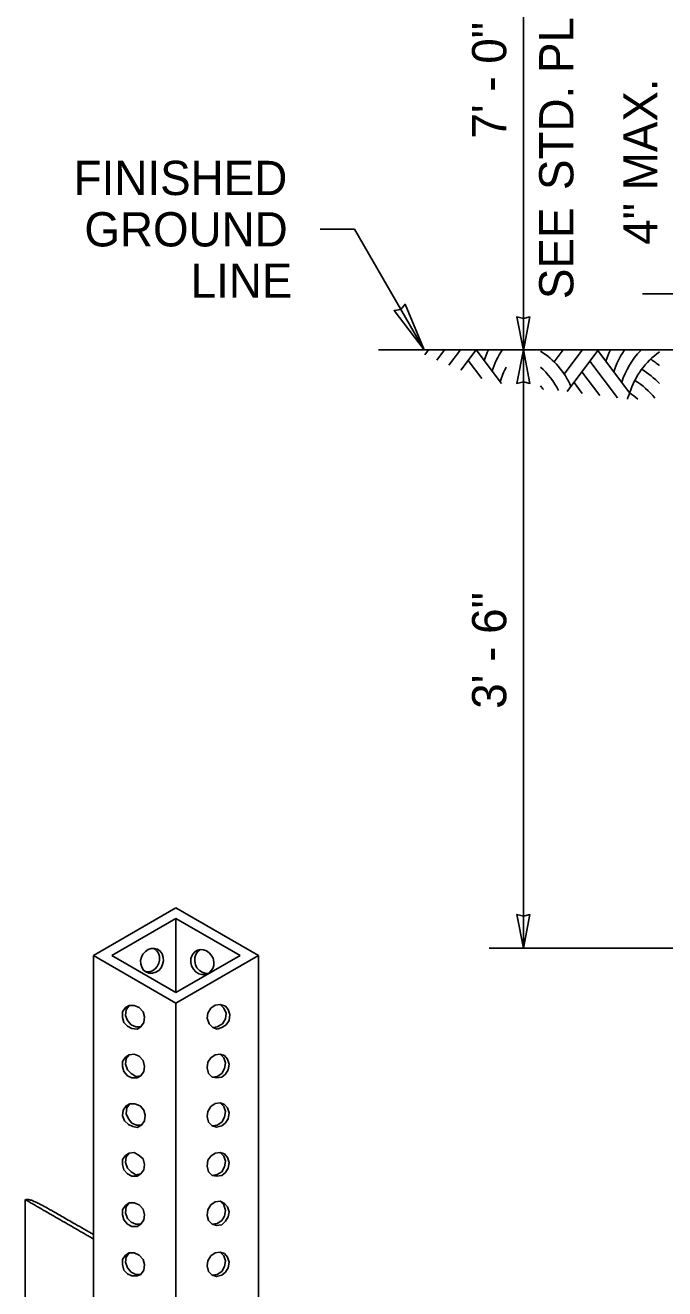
# Model space of a CAD drawing. Extents: x 99862 to 103680, y 99470 to 102076.
# Drawn here: x 101650 to 101949, y 100895 to 101485 of the extents above; entities that cross this region are included whole.
import ezdxf

# ---------------------------------------------------------------- set-up
doc = ezdxf.new("R2010")
doc.units = 0
for name, color, linetype in [('Level 1', 7, 'Continuous'), ('Level 15', 7, 'Continuous'), ('Level 2', 7, 'Continuous'), ('Level 20', 7, 'Continuous'), ('Level 27', 7, 'Continuous'), ('Level 4', 7, 'Continuous'), ('Level 5', 7, 'Continuous')]:
    doc.layers.add(name, color=color, linetype=linetype)

msp = doc.modelspace()

# ---------------------------------------------------------------- linework, layer by layer
at = {"layer": 'Level 1'}
for p, q in [((101837.2, 101331.35), (101838.99, 101333.74)), ((101842.83, 101328.96), (101846.41, 101333.74)), ((101848.46, 101326.57), (101853.84, 101333.74)), ((101854.09, 101324.18), (101861.26, 101333.74)), ((101861.26, 101333.74), (101873.05, 101318.02)), ((101857.55, 101328.79), (101863.91, 101320.31))]:
    msp.add_line(p, q, dxfattribs=at)
for centre, start, end in [((101810.6, 101302.55), 56.0955, 56.09634), ((101900.78, 101317.4), 154.22656, 162.3566), ((101904.5, 101312.45), 145.49104, 162.3566), ((101871.19, 101301.38), 23.9418, 57.64973), ((101908.21, 101307.5), 151.13992, 162.3566), ((101866.29, 101297.6), 27.04099, 48.27306), ((101862.58, 101292.65), 36.71615, 40.14882)]:
    msp.add_arc(centre, 37.58, start, end, dxfattribs=at)
at = {"layer": 'Level 15'}
for p, q in [((101804.37, 101390.03), (101788.37, 101390.03)), ((101836.87, 101333.74), (101804.37, 101390.03))]:
    msp.add_line(p, q, dxfattribs=at)
for points in [[(101883.3, 101634.09), (101883.3, 101333.39)], [(101938.91, 101359.95), (102030.24, 101359.95)], [(101883.3, 101333.74), (101883.3, 101054.17)], [(101867.3, 101054.17), (101993.49, 101054.17)]]:
    msp.add_lwpolyline(points, dxfattribs=at)
for points in [[(101836.87, 101333.74), (101822.87, 101352.02), (101825.98, 101352.59), (101828.04, 101355)], [(101883.3, 101333.39), (101886.38, 101349.12), (101883.3, 101348.39), (101880.22, 101349.12)], [(101883.3, 101333.74), (101886.38, 101318.01), (101883.3, 101318.74), (101880.22, 101318.01)], [(101883.3, 101054.17), (101886.38, 101069.89), (101883.3, 101069.17), (101880.22, 101069.89)]]:
    msp.add_lwpolyline(points, close=True, dxfattribs=at)
at = {"layer": 'Level 2'}
for p, q in [((101682.38, 101050.75), (101720.9, 101072.98)), ((101690.94, 101050.75), (101720.9, 101068.04)), ((101720.8, 101068.1), (101720.8, 101033.93)), ((101720.9, 101072.98), (101759.42, 101050.75)), ((101720.9, 101068.04), (101750.86, 101050.75)), ((101720.9, 101028.51), (101682.38, 101050.75)), ((101682.38, 100920.34), (101682.38, 101050.75)), ((101720.9, 101033.45), (101690.94, 101050.75)), ((101759.42, 101050.75), (101720.9, 101028.51)), ((101750.86, 101050.75), (101720.9, 101033.45)), ((101759.42, 100875.03), (101759.42, 101050.75)), ((101697.28, 101026.43), (101695.9, 101024.42)), ((101698.99, 101027.43), (101697.28, 101026.43)), ((101698.99, 101027.43), (101697.62, 101025.42)), ((101697.62, 101025.42), (101698.99, 101027.43)), ((101701.39, 101027.43), (101698.99, 101027.43)), ((101703.79, 101026.43), (101701.39, 101027.43)), ((101705.51, 101024.42), (101703.79, 101026.43)), ((101720.9, 100850.43), (101720.9, 101028.51)), ((101739.21, 101027.46), (101737.16, 101026.12)), ((101741.62, 101027.79), (101739.21, 101027.46)), ((101743.33, 101026.12), (101741.62, 101027.79)), ((101741.62, 101027.79), (101743.33, 101026.12)), ((101744.02, 101027.12), (101741.62, 101027.79)), ((101745.39, 101025.45), (101744.02, 101027.12)), ((101695.9, 101024.42), (101695.9, 101021.74)), ((101695.9, 101021.74), (101696.59, 101019.39)), ((101697.62, 101025.42), (101697.28, 101022.74)), ((101697.28, 101022.74), (101697.62, 101025.42)), ((101697.28, 101022.74), (101698.3, 101020.39)), ((101698.3, 101020.39), (101697.28, 101022.74)), ((101698.3, 101020.39), (101700.02, 101018.38)), ((101700.02, 101018.38), (101698.3, 101020.39)), ((101706.19, 101022.07), (101705.51, 101024.42)), ((101705.85, 101019.39), (101706.19, 101022.07)), ((101735.78, 101023.77), (101735.44, 101021.42)), ((101735.44, 101021.42), (101736.47, 101018.74)), ((101737.16, 101026.12), (101735.78, 101023.77)), ((101742.65, 101018.74), (101744.02, 101021.09)), ((101744.02, 101021.09), (101742.65, 101018.74)), ((101744.36, 101023.77), (101743.33, 101026.12)), ((101743.33, 101026.12), (101744.36, 101023.77)), ((101744.02, 101021.09), (101744.36, 101023.77)), ((101744.36, 101023.77), (101744.02, 101021.09)), ((101744.36, 101018.41), (101745.73, 101020.42)), ((101746.08, 101023.1), (101745.39, 101025.45)), ((101745.73, 101020.42), (101746.08, 101023.1)), ((101696.59, 101019.39), (101698.3, 101017.71)), ((101698.3, 101017.71), (101700.36, 101016.71)), ((101700.02, 101018.38), (101702.08, 101017.38)), ((101702.08, 101017.38), (101700.02, 101018.38)), ((101700.36, 101016.71), (101702.76, 101016.37)), ((101702.08, 101017.38), (101704.48, 101017.38)), ((101704.48, 101017.38), (101702.08, 101017.38)), ((101702.76, 101016.37), (101704.48, 101017.38)), ((101704.48, 101017.38), (101705.85, 101019.39)), ((101736.47, 101018.74), (101738.19, 101017.07)), ((101738.19, 101017.07), (101740.24, 101017.4)), ((101740.24, 101017.4), (101738.19, 101017.07)), ((101738.19, 101017.07), (101740.24, 101016.39)), ((101740.24, 101017.4), (101742.65, 101018.74)), ((101742.65, 101018.74), (101740.24, 101017.4)), ((101740.24, 101016.39), (101742.3, 101017.07)), ((101742.3, 101017.07), (101744.36, 101018.41)), ((101697.28, 101003.3), (101695.9, 101001.29)), ((101698.99, 101004.3), (101697.28, 101003.3)), ((101697.62, 101002.63), (101697.28, 100999.95)), ((101697.28, 100999.95), (101697.62, 101002.63)), ((101698.99, 101004.3), (101697.62, 101002.63)), ((101697.62, 101002.63), (101698.99, 101004.3)), ((101701.39, 101004.64), (101698.99, 101004.3)), ((101703.79, 101003.63), (101701.39, 101004.64)), ((101705.51, 101001.62), (101703.79, 101003.63)), ((101737.16, 101002.99), (101735.78, 101000.98)), ((101739.21, 101004.33), (101737.16, 101002.99)), ((101741.62, 101004.66), (101739.21, 101004.33)), ((101743.33, 101002.99), (101741.62, 101004.66)), ((101743.67, 101003.99), (101741.62, 101004.66)), ((101741.62, 101004.66), (101743.33, 101002.99)), ((101744.02, 101000.64), (101743.33, 101002.99)), ((101743.33, 101002.99), (101744.02, 101000.64)), ((101745.05, 101002.32), (101743.67, 101003.99)), ((101695.9, 101001.29), (101695.9, 100998.94)), ((101695.9, 100998.94), (101696.59, 100996.59)), ((101697.28, 100999.95), (101698.3, 100997.26)), ((101698.3, 100997.26), (101697.28, 100999.95)), ((101698.3, 100997.26), (101700.02, 100995.59)), ((101700.02, 100995.59), (101698.3, 100997.26)), ((101706.19, 100998.94), (101705.51, 101001.62)), ((101705.85, 100996.59), (101706.19, 100998.94)), ((101735.78, 101000.98), (101735.44, 100998.29)), ((101735.44, 100998.29), (101736.13, 100995.61)), ((101742.3, 100995.61), (101743.67, 100997.96)), ((101743.67, 100997.96), (101742.3, 100995.61)), ((101743.67, 100997.96), (101744.02, 101000.64)), ((101744.02, 101000.64), (101743.67, 100997.96)), ((101744.02, 100995.28), (101745.39, 100997.29)), ((101745.73, 100999.97), (101745.05, 101002.32)), ((101745.39, 100997.29), (101745.73, 100999.97)), ((101696.59, 100996.59), (101698.3, 100994.58)), ((101698.3, 100994.58), (101700.36, 100993.58)), ((101700.02, 100995.59), (101702.08, 100994.25)), ((101702.08, 100994.25), (101700.02, 100995.59)), ((101700.36, 100993.58), (101702.76, 100993.58)), ((101702.08, 100994.25), (101704.48, 100994.58)), ((101704.48, 100994.58), (101702.08, 100994.25)), ((101702.76, 100993.58), (101704.48, 100994.58)), ((101704.48, 100994.58), (101705.85, 100996.59)), ((101736.13, 100995.61), (101737.84, 100993.94)), ((101737.84, 100993.94), (101740.24, 100994.27)), ((101740.24, 100994.27), (101737.84, 100993.94)), ((101737.84, 100993.94), (101739.9, 100993.6)), ((101739.9, 100993.6), (101742.3, 100993.94)), ((101740.24, 100994.27), (101742.3, 100995.61)), ((101742.3, 100995.61), (101740.24, 100994.27)), ((101742.3, 100993.94), (101744.02, 100995.28)), ((101697.62, 100980.5), (101696.25, 100978.49)), ((101699.33, 100981.51), (101697.62, 100980.5)), ((101697.96, 100979.5), (101697.62, 100976.82)), ((101697.62, 100976.82), (101697.96, 100979.5)), ((101699.33, 100981.51), (101697.96, 100979.5)), ((101697.96, 100979.5), (101699.33, 100981.51)), ((101701.74, 100981.51), (101699.33, 100981.51)), ((101704.14, 100980.5), (101701.74, 100981.51)), ((101705.85, 100978.49), (101704.14, 100980.5)), ((101737.16, 100980.19), (101735.78, 100977.85)), ((101739.21, 100981.53), (101737.16, 100980.19)), ((101741.62, 100981.87), (101739.21, 100981.53)), ((101743.33, 100980.19), (101741.62, 100981.87)), ((101743.67, 100981.2), (101741.62, 100981.87)), ((101741.62, 100981.87), (101743.33, 100980.19)), ((101744.02, 100977.85), (101743.33, 100980.19)), ((101743.33, 100980.19), (101744.02, 100977.85)), ((101745.05, 100979.52), (101743.67, 100981.2)), ((101745.73, 100977.17), (101745.05, 100979.52)), ((101696.25, 100978.49), (101695.9, 100975.81)), ((101695.9, 100975.81), (101696.93, 100973.46)), ((101696.93, 100973.46), (101698.65, 100971.79)), ((101697.62, 100976.82), (101698.65, 100974.47)), ((101698.65, 100974.47), (101697.62, 100976.82)), ((101698.65, 100974.47), (101700.36, 100972.46)), ((101700.36, 100972.46), (101698.65, 100974.47)), ((101704.82, 100971.45), (101706.19, 100973.46)), ((101706.54, 100976.15), (101705.85, 100978.49)), ((101706.19, 100973.46), (101706.54, 100976.15)), ((101735.78, 100977.85), (101735.44, 100975.5)), ((101735.44, 100975.5), (101736.13, 100972.82)), ((101742.3, 100972.82), (101743.67, 100975.16)), ((101743.67, 100975.16), (101742.3, 100972.82)), ((101743.67, 100975.16), (101744.02, 100977.85)), ((101744.02, 100977.85), (101743.67, 100975.16)), ((101744.02, 100972.48), (101745.39, 100974.49)), ((101745.39, 100974.49), (101745.73, 100977.17)), ((101698.65, 100971.79), (101700.71, 100970.78)), ((101700.36, 100972.46), (101702.42, 100971.45)), ((101702.42, 100971.45), (101700.36, 100972.46)), ((101700.71, 100970.78), (101702.76, 100970.45)), ((101702.42, 100971.45), (101704.82, 100971.45)), ((101704.82, 100971.45), (101702.42, 100971.45)), ((101702.76, 100970.45), (101704.82, 100971.45)), ((101736.13, 100972.82), (101737.84, 100971.14)), ((101737.84, 100971.14), (101740.24, 100971.48)), ((101740.24, 100971.48), (101737.84, 100971.14)), ((101737.84, 100971.14), (101739.9, 100970.47)), ((101739.9, 100970.47), (101742.3, 100971.14)), ((101740.24, 100971.48), (101742.3, 100972.82)), ((101742.3, 100972.82), (101740.24, 100971.48)), ((101742.3, 100971.14), (101744.02, 100972.48)), ((101697.28, 100957.37), (101695.9, 100955.36)), ((101698.99, 100958.38), (101697.28, 100957.37)), ((101697.62, 100956.7), (101697.28, 100954.02)), ((101697.28, 100954.02), (101697.62, 100956.7)), ((101698.99, 100958.38), (101697.62, 100956.7)), ((101697.62, 100956.7), (101698.99, 100958.38)), ((101701.39, 100958.71), (101698.99, 100958.38)), ((101703.79, 100957.37), (101701.39, 100958.71)), ((101705.51, 100955.7), (101703.79, 100957.37)), ((101706.19, 100953.02), (101705.51, 100955.7)), ((101737.16, 100957.06), (101735.78, 100955.05)), ((101739.21, 100958.4), (101737.16, 100957.06)), ((101741.62, 100958.74), (101739.21, 100958.4)), ((101743.33, 100957.06), (101741.62, 100958.74)), ((101743.67, 100958.07), (101741.62, 100958.74)), ((101741.62, 100958.74), (101743.33, 100957.06)), ((101744.02, 100954.72), (101743.33, 100957.06)), ((101743.33, 100957.06), (101744.02, 100954.72)), ((101745.05, 100956.39), (101743.67, 100958.07)), ((101745.73, 100954.05), (101745.05, 100956.39)), ((101695.9, 100955.36), (101695.9, 100953.02)), ((101695.9, 100953.02), (101696.59, 100950.67)), ((101696.59, 100950.67), (101698.3, 100948.66)), ((101697.28, 100954.02), (101698.3, 100951.34)), ((101698.3, 100951.34), (101697.28, 100954.02)), ((101698.3, 100951.34), (101700.02, 100949.66)), ((101700.02, 100949.66), (101698.3, 100951.34)), ((101700.02, 100949.66), (101702.08, 100948.32)), ((101702.08, 100948.32), (101700.02, 100949.66)), ((101704.48, 100948.66), (101705.85, 100950.67)), ((101705.85, 100950.67), (101706.19, 100953.02)), ((101735.78, 100955.05), (101735.44, 100952.37)), ((101735.44, 100952.37), (101736.13, 100949.69)), ((101736.13, 100949.69), (101737.84, 100948.01)), ((101740.24, 100948.35), (101742.3, 100949.69)), ((101742.3, 100949.69), (101740.24, 100948.35)), ((101742.3, 100949.69), (101743.67, 100952.03)), ((101743.67, 100952.03), (101742.3, 100949.69)), ((101743.67, 100952.03), (101744.02, 100954.72)), ((101744.02, 100954.72), (101743.67, 100952.03)), ((101744.02, 100949.35), (101745.39, 100951.36)), ((101745.39, 100951.36), (101745.73, 100954.05)), ((101698.3, 100948.66), (101700.36, 100947.65)), ((101700.36, 100947.65), (101702.76, 100947.65)), ((101702.08, 100948.32), (101704.48, 100948.66)), ((101704.48, 100948.66), (101702.08, 100948.32)), ((101702.76, 100947.65), (101704.48, 100948.66)), ((101737.84, 100948.01), (101740.24, 100948.35)), ((101740.24, 100948.35), (101737.84, 100948.01)), ((101737.84, 100948.01), (101739.9, 100947.68)), ((101739.9, 100947.68), (101742.3, 100948.01)), ((101742.3, 100948.01), (101744.02, 100949.35)), ((101697.28, 100933.91), (101695.9, 100931.9)), ((101695.9, 100931.9), (101695.9, 100929.55)), ((101698.99, 100935.25), (101697.28, 100933.91)), ((101697.62, 100933.24), (101697.28, 100930.56)), ((101697.28, 100930.56), (101697.62, 100933.24)), ((101698.99, 100935.25), (101697.62, 100933.24)), ((101697.62, 100933.24), (101698.99, 100935.25)), ((101701.39, 100935.25), (101698.99, 100935.25)), ((101703.79, 100934.24), (101701.39, 100935.25)), ((101705.51, 100932.23), (101703.79, 100934.24)), ((101706.19, 100929.55), (101705.51, 100932.23)), ((101735.78, 100931.92), (101735.44, 100929.24)), ((101737.16, 100934.27), (101735.78, 100931.92)), ((101739.21, 100935.61), (101737.16, 100934.27)), ((101741.62, 100935.94), (101739.21, 100935.61)), ((101743.33, 100934.27), (101741.62, 100935.94)), ((101743.67, 100934.94), (101741.62, 100935.94)), ((101741.62, 100935.94), (101743.33, 100934.27)), ((101744.02, 100931.59), (101743.33, 100934.27)), ((101743.33, 100934.27), (101744.02, 100931.59)), ((101745.05, 100933.26), (101743.67, 100934.94)), ((101745.73, 100930.92), (101745.05, 100933.26)), ((101695.9, 100929.55), (101696.59, 100927.2)), ((101696.59, 100927.2), (101698.3, 100925.19)), ((101697.28, 100930.56), (101698.3, 100927.88)), ((101698.3, 100927.88), (101697.28, 100930.56)), ((101698.3, 100927.88), (101700.02, 100926.2)), ((101700.02, 100926.2), (101698.3, 100927.88)), ((101700.02, 100926.2), (101702.08, 100925.19)), ((101702.08, 100925.19), (101700.02, 100926.2)), ((101704.48, 100925.19), (101705.85, 100927.2)), ((101705.85, 100927.2), (101706.19, 100929.55)), ((101735.44, 100929.24), (101736.13, 100926.89)), ((101736.13, 100926.89), (101737.84, 100925.22)), ((101740.24, 100925.55), (101742.3, 100926.89)), ((101742.3, 100926.89), (101740.24, 100925.55)), ((101742.3, 100926.89), (101743.67, 100928.9)), ((101743.67, 100928.9), (101742.3, 100926.89)), ((101742.3, 100924.88), (101744.02, 100926.56)), ((101743.67, 100928.9), (101744.02, 100931.59)), ((101744.02, 100931.59), (101743.67, 100928.9)), ((101744.02, 100926.56), (101745.39, 100928.57)), ((101745.39, 100928.57), (101745.73, 100930.92)), ((101682.38, 100920.34), (101682.38, 100873.79)), ((101698.3, 100925.19), (101700.36, 100924.19)), ((101700.36, 100924.19), (101702.76, 100924.19)), ((101702.08, 100925.19), (101704.48, 100925.19)), ((101704.48, 100925.19), (101702.08, 100925.19)), ((101702.76, 100924.19), (101704.48, 100925.19)), ((101737.84, 100925.22), (101740.24, 100925.55)), ((101740.24, 100925.55), (101737.84, 100925.22)), ((101737.84, 100925.22), (101739.9, 100924.55)), ((101739.9, 100924.55), (101742.3, 100924.88)), ((101697.28, 100910.78), (101695.9, 100908.77)), ((101695.9, 100908.77), (101695.9, 100906.42)), ((101698.99, 100911.79), (101697.28, 100910.78)), ((101697.62, 100909.77), (101697.28, 100907.43)), ((101697.28, 100907.43), (101697.62, 100909.77)), ((101698.99, 100911.79), (101697.62, 100909.77)), ((101697.62, 100909.77), (101698.99, 100911.79)), ((101701.39, 100911.79), (101698.99, 100911.79)), ((101703.79, 100910.78), (101701.39, 100911.79)), ((101705.51, 100908.77), (101703.79, 100910.78)), ((101706.19, 100906.42), (101705.51, 100908.77)), ((101737.16, 100910.47), (101735.78, 100908.12)), ((101739.21, 100911.81), (101737.16, 100910.47)), ((101741.62, 100912.14), (101739.21, 100911.81)), ((101743.33, 100910.47), (101741.62, 100912.14)), ((101743.67, 100911.47), (101741.62, 100912.14)), ((101741.62, 100912.14), (101743.33, 100910.47)), ((101744.02, 100908.12), (101743.33, 100910.47)), ((101743.33, 100910.47), (101744.02, 100908.12)), ((101745.05, 100909.8), (101743.67, 100911.47)), ((101745.73, 100907.45), (101745.05, 100909.8)), ((101695.9, 100906.42), (101696.59, 100903.74)), ((101696.59, 100903.74), (101698.3, 100902.06)), ((101697.28, 100907.43), (101698.3, 100904.75)), ((101698.3, 100904.75), (101697.28, 100907.43)), ((101698.3, 100904.75), (101700.02, 100902.73)), ((101700.02, 100902.73), (101698.3, 100904.75)), ((101700.02, 100902.73), (101702.08, 100901.73)), ((101702.08, 100901.73), (101700.02, 100902.73)), ((101704.48, 100901.73), (101705.85, 100903.74)), ((101705.85, 100903.74), (101706.19, 100906.42)), ((101735.78, 100908.12), (101735.44, 100905.77)), ((101735.44, 100905.77), (101736.13, 100903.09)), ((101736.13, 100903.09), (101737.84, 100901.42)), ((101740.24, 100901.75), (101742.3, 100903.09)), ((101742.3, 100903.09), (101740.24, 100901.75)), ((101742.3, 100903.09), (101743.67, 100905.44)), ((101743.67, 100905.44), (101742.3, 100903.09)), ((101742.3, 100901.42), (101744.02, 100902.76)), ((101743.67, 100905.44), (101744.02, 100908.12)), ((101744.02, 100908.12), (101743.67, 100905.44)), ((101744.02, 100902.76), (101745.39, 100904.77)), ((101745.39, 100904.77), (101745.73, 100907.45)), ((101698.3, 100902.06), (101700.36, 100901.06)), ((101700.36, 100901.06), (101702.76, 100901.06)), ((101702.08, 100901.73), (101704.48, 100901.73)), ((101704.48, 100901.73), (101702.08, 100901.73)), ((101702.76, 100901.06), (101704.48, 100901.73)), ((101737.84, 100901.42), (101740.24, 100901.75)), ((101740.24, 100901.75), (101737.84, 100901.42)), ((101737.84, 100901.42), (101739.9, 100900.75)), ((101739.9, 100900.75), (101742.3, 100901.42))]:
    msp.add_line(p, q, dxfattribs=at)
for points in [[(101706.88, 101043.08), (101708.45, 101043.08), (101709.87, 101043.64), (101711.14, 101044.47), (101712.14, 101045.58), (101712.85, 101047.11), (101713.27, 101048.63), (101713.27, 101050.3), (101712.71, 101051.83), (101711.85, 101053.07), (101710.72, 101054.05), (101709.3, 101054.05), (101707.88, 101053.49), (101706.6, 101052.66), (101705.46, 101051.41), (101704.75, 101050.02), (101704.33, 101048.36), (101704.47, 101046.83), (101704.9, 101045.3), (101705.75, 101043.92), (101706.88, 101043.08)], [(101706.88, 101043.08), (101708.3, 101042.53), (101709.87, 101042.53), (101711.43, 101042.95), (101712.85, 101043.78), (101713.98, 101045.03), (101714.69, 101046.55), (101715.12, 101048.22), (101714.98, 101049.88), (101714.41, 101051.55), (101713.56, 101052.8), (101712.28, 101053.63), (101710.72, 101054.05), (101711.85, 101053.07), (101712.71, 101051.83), (101713.27, 101050.3), (101713.27, 101048.63), (101712.85, 101047.11), (101712.14, 101045.58), (101711.14, 101044.47), (101709.87, 101043.64), (101708.45, 101043.08), (101706.88, 101043.08)], [(101735.99, 101042.39), (101734.57, 101041.84), (101733.01, 101041.84), (101731.59, 101042.25), (101730.17, 101043.08), (101729.04, 101044.33), (101728.18, 101045.86), (101727.9, 101047.52), (101727.9, 101049.33), (101728.47, 101050.85), (101729.46, 101052.1), (101730.74, 101053.07), (101732.3, 101053.49), (101731.02, 101052.52), (101730.17, 101051.27), (101729.75, 101049.74), (101729.75, 101048.08), (101730.03, 101046.41), (101730.74, 101045.03), (101731.88, 101043.78), (101733.15, 101042.95), (101734.57, 101042.53), (101735.99, 101042.39)], [(101735.99, 101042.39), (101734.57, 101042.53), (101733.15, 101042.95), (101731.88, 101043.78), (101730.74, 101045.03), (101730.03, 101046.41), (101729.75, 101048.08), (101729.75, 101049.74), (101730.17, 101051.27), (101731.02, 101052.52), (101732.3, 101053.49), (101733.72, 101053.35), (101735.14, 101052.94), (101736.42, 101051.96), (101737.41, 101050.85), (101738.26, 101049.47), (101738.55, 101047.8), (101738.55, 101046.14), (101738.12, 101044.61), (101737.13, 101043.36), (101735.99, 101042.39)]]:
    msp.add_lwpolyline(points, dxfattribs=at)
at = {"layer": 'Level 27'}
for p, q in [((101897.65, 101328.06), (101901.91, 101333.74)), ((101902.39, 101322.33), (101910.68, 101333.38)), ((101903.8, 101314.3), (101918.11, 101333.38)), ((101918.11, 101333.38), (101932.96, 101313.59)), ((101914.39, 101328.43), (101927.29, 101311.24)), ((101910.68, 101323.49), (101919.06, 101312.31)), ((101906.97, 101318.53), (101910.83, 101313.39))]:
    msp.add_line(p, q, dxfattribs=at)
for centre, start, end in [((101957.63, 101317.05), 154.22656, 162.3566), ((101961.34, 101312.1), 145.49104, 162.3566), ((101965.05, 101307.15), 135.71272, 162.3566), ((101968.77, 101302.2), 125.56218, 162.3566), ((101923.13, 101297.25), 50.74302, 58.54646), ((101919.42, 101292.3), 42.98009, 59.30215), ((101915.71, 101287.35), 39.2511, 58.48737), ((101897.15, 101324.98), 337.57965, 342.3566), ((101912, 101282.4), 48.77427, 56.09639)]:
    msp.add_arc(centre, 37.58, start, end, dxfattribs=at)
at = {"layer": 'Level 4'}
msp.add_line((101650.47, 100810.89), (101650.47, 100936.69), dxfattribs=at)
for points, degree in [([(101682.38, 100920.34), (101668.22, 100928.52), (101654.07, 100936.69), (101652.27, 100936.69), (101650.47, 100936.69), (101650.59, 100936.62), (101650.71, 100936.55)], 4), ([(101650.78, 100936.51), (101666.58, 100927.39), (101682.38, 100918.27)], 2)]:
    msp.add_open_spline(points, degree=degree, dxfattribs=at)
at = {"layer": 'Level 5'}
msp.add_lwpolyline([(102037.4, 101333.74), (101815.56, 101333.74)], dxfattribs=at)

# ---------------------------------------------------------------- texts
at = {"layer": 'Level 20'}
for s, p in [('STD. PLAN G-20.10', (101906.67, 101408.37)), (' 7\' - 0" MIN.', (101875.3, 101426.46)), ('4" MAX. ', (101945.96, 101382.8)), ('SEE ', (101906.67, 101357.41)), ('3\' - 6"', (101875.3, 101166.02))]:
    msp.add_text(s, height=16, rotation=90, dxfattribs=at).set_placement(p)
for s, p in [('FINISHED', (101673.11, 101406.03)), ('GROUND', (101678.08, 101382.03)), ('LINE', (101727.75, 101358.03))]:
    msp.add_text(s, height=16, dxfattribs=at).set_placement(p)

doc.saveas('drawing.dxf')
